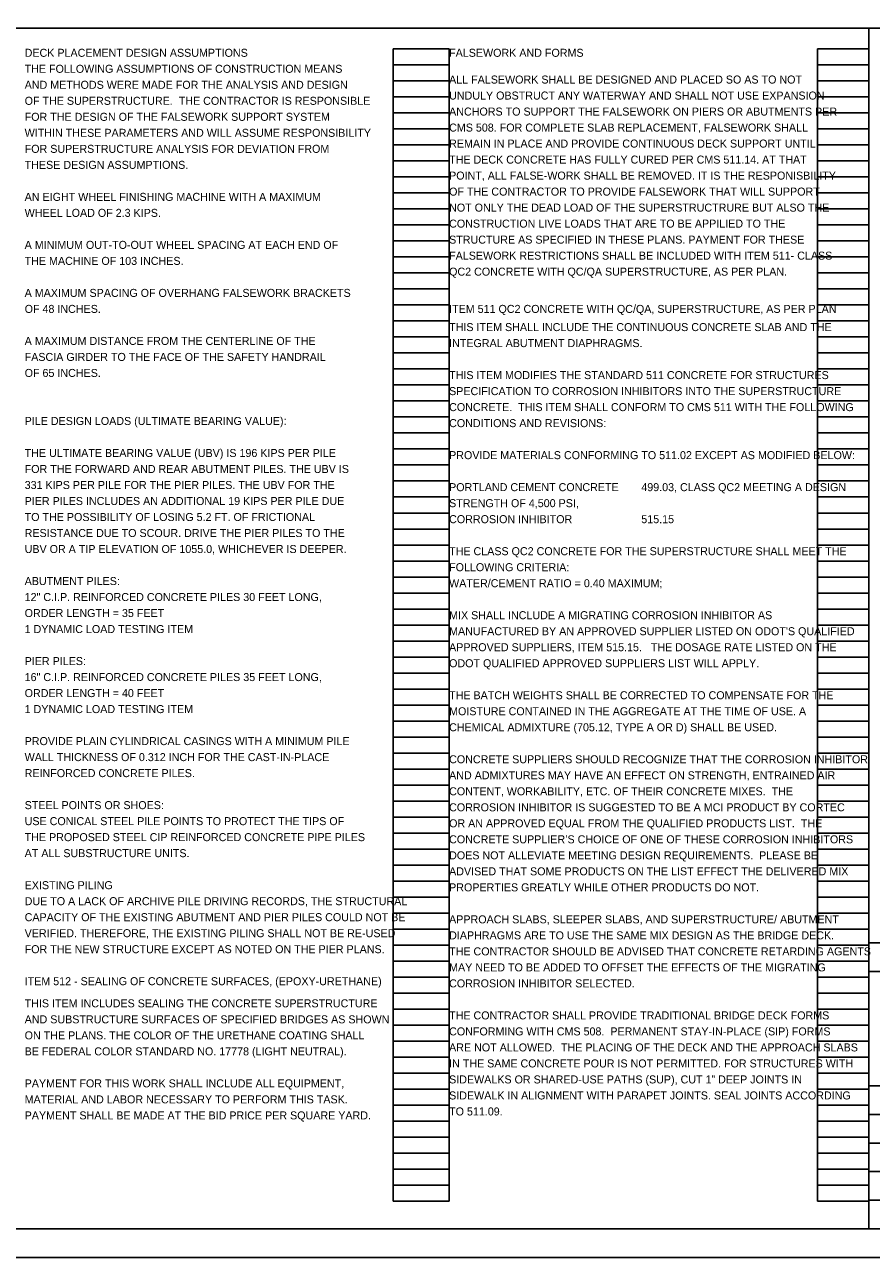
# Model space of a CAD drawing. Extents: x -15 to 144, y -80 to 40.
# Drawn here: x 17.24 to 32.04, y 0 to 21.56 of the extents above; entities that cross this region are included whole.
import ezdxf

# ---------------------------------------------------------------- set-up
doc = ezdxf.new("R2010")
doc.units = 0
for name, color, linetype in [('BR_P_Gen_Text', 7, 'Continuous'), ('Default', 7, 'Continuous'), ('SH_Cut_Line', 7, 'Continuous'), ('SH_Data', 7, 'Continuous'), ('SH_Text', 7, 'Continuous')]:
    doc.layers.add(name, color=color, linetype=linetype)

msp = doc.modelspace()

# ---------------------------------------------------------------- linework, layer by layer
at = {"layer": 'SH_Cut_Line'}
msp.add_lwpolyline([(0, 0), (34, 0), (34, 22), (0, 22)], close=True, dxfattribs=at)
at = {"layer": 'SH_Data'}
for p, q in [((32, 0.5), (32, 21.5)), ((32, 5.5), (33.5, 5.5)), ((32, 5), (33.5, 5)), ((32, 3), (33.5, 3)), ((32, 2.5), (33.5, 2.5)), ((32, 2), (33.5, 2)), ((32, 1.5), (33.5, 1.5)), ((32, 1), (33.5, 1))]:
    msp.add_line(p, q, dxfattribs=at)
msp.add_lwpolyline([(1.5, 21.5), (33.5, 21.5), (33.5, 0.5), (1.5, 0.5)], close=True, dxfattribs=at)
at = {"layer": 'SH_Text'}
for p, q in [((23.68, 0.98), (23.68, 21.14)), ((23.68, 21.14), (24.66, 21.14)), ((24.66, 0.98), (24.66, 21.14)), ((31.1, 0.98), (31.1, 21.14)), ((31.1, 21.14), (32, 21.14)), ((32, 0.98), (32, 21.14)), ((23.68, 20.86), (24.66, 20.86)), ((31.1, 20.86), (32, 20.86)), ((23.68, 20.58), (24.66, 20.58)), ((31.1, 20.58), (32, 20.58)), ((23.68, 20.3), (24.66, 20.3)), ((31.1, 20.3), (32, 20.3)), ((23.68, 20.02), (24.66, 20.02)), ((31.1, 20.02), (32, 20.02)), ((23.68, 19.74), (24.66, 19.74)), ((31.1, 19.74), (32, 19.74)), ((23.68, 19.46), (24.66, 19.46)), ((31.1, 19.46), (32, 19.46)), ((23.68, 19.18), (24.66, 19.18)), ((31.1, 19.18), (32, 19.18)), ((23.68, 18.9), (24.66, 18.9)), ((31.1, 18.9), (32, 18.9)), ((23.68, 18.62), (24.66, 18.62)), ((31.1, 18.62), (32, 18.62)), ((23.68, 18.34), (24.66, 18.34)), ((31.1, 18.34), (32, 18.34)), ((23.68, 18.06), (24.66, 18.06)), ((31.1, 18.06), (32, 18.06)), ((23.68, 17.78), (24.66, 17.78)), ((31.1, 17.78), (32, 17.78)), ((23.68, 17.5), (24.66, 17.5)), ((31.1, 17.5), (32, 17.5)), ((23.68, 17.22), (24.66, 17.22)), ((31.1, 17.22), (32, 17.22)), ((23.68, 16.94), (24.66, 16.94)), ((31.1, 16.94), (32, 16.94)), ((23.68, 16.66), (24.66, 16.66)), ((31.1, 16.66), (32, 16.66)), ((23.68, 16.38), (24.66, 16.38)), ((31.1, 16.38), (32, 16.38)), ((23.68, 16.1), (24.66, 16.1)), ((31.1, 16.1), (32, 16.1)), ((23.68, 15.82), (24.66, 15.82)), ((31.1, 15.82), (32, 15.82)), ((23.68, 15.54), (24.66, 15.54)), ((31.1, 15.54), (32, 15.54)), ((23.68, 15.26), (24.66, 15.26)), ((31.1, 15.26), (32, 15.26)), ((23.68, 14.98), (24.66, 14.98)), ((31.1, 14.98), (32, 14.98)), ((23.68, 14.7), (24.66, 14.7)), ((31.1, 14.7), (32, 14.7)), ((23.68, 14.42), (24.66, 14.42)), ((31.1, 14.42), (32, 14.42)), ((23.68, 14.14), (24.66, 14.14)), ((31.1, 14.14), (32, 14.14)), ((23.68, 13.86), (24.66, 13.86)), ((31.1, 13.86), (32, 13.86)), ((23.68, 13.58), (24.66, 13.58)), ((31.1, 13.58), (32, 13.58)), ((23.68, 13.3), (24.66, 13.3)), ((31.1, 13.3), (32, 13.3)), ((23.68, 13.02), (24.66, 13.02)), ((31.1, 13.02), (32, 13.02)), ((23.68, 12.74), (24.66, 12.74)), ((31.1, 12.74), (32, 12.74)), ((23.68, 12.46), (24.66, 12.46)), ((31.1, 12.46), (32, 12.46)), ((23.68, 12.18), (24.66, 12.18)), ((31.1, 12.18), (32, 12.18)), ((23.68, 11.9), (24.66, 11.9)), ((31.1, 11.9), (32, 11.9)), ((23.68, 11.62), (24.66, 11.62)), ((31.1, 11.62), (32, 11.62)), ((23.68, 11.34), (24.66, 11.34)), ((31.1, 11.34), (32, 11.34)), ((23.68, 11.06), (24.66, 11.06)), ((31.1, 11.06), (32, 11.06)), ((23.68, 10.78), (24.66, 10.78)), ((31.1, 10.78), (32, 10.78)), ((23.68, 10.5), (24.66, 10.5)), ((31.1, 10.5), (32, 10.5)), ((23.68, 10.22), (24.66, 10.22)), ((31.1, 10.22), (32, 10.22)), ((23.68, 9.94), (24.66, 9.94)), ((31.1, 9.94), (32, 9.94)), ((23.68, 9.66), (24.66, 9.66)), ((31.1, 9.66), (32, 9.66)), ((23.68, 9.38), (24.66, 9.38)), ((31.1, 9.38), (32, 9.38)), ((23.68, 9.1), (24.66, 9.1)), ((31.1, 9.1), (32, 9.1)), ((23.68, 8.82), (24.66, 8.82)), ((31.1, 8.82), (32, 8.82)), ((23.68, 8.54), (24.66, 8.54)), ((31.1, 8.54), (32, 8.54)), ((23.68, 8.26), (24.66, 8.26)), ((31.1, 8.26), (32, 8.26)), ((23.68, 7.98), (24.66, 7.98)), ((31.1, 7.98), (32, 7.98)), ((23.68, 7.7), (24.66, 7.7)), ((31.1, 7.7), (32, 7.7)), ((23.68, 7.42), (24.66, 7.42)), ((31.1, 7.42), (32, 7.42)), ((23.68, 7.14), (24.66, 7.14)), ((31.1, 7.14), (32, 7.14)), ((23.68, 6.86), (24.66, 6.86)), ((31.1, 6.86), (32, 6.86)), ((23.68, 6.58), (24.66, 6.58)), ((31.1, 6.58), (32, 6.58)), ((23.68, 6.3), (24.66, 6.3)), ((31.1, 6.3), (32, 6.3)), ((23.68, 6.02), (24.66, 6.02)), ((31.1, 6.02), (32, 6.02)), ((23.68, 5.74), (24.66, 5.74)), ((31.1, 5.74), (32, 5.74)), ((23.68, 5.46), (24.66, 5.46)), ((31.1, 5.46), (32, 5.46)), ((23.68, 5.18), (24.66, 5.18)), ((31.1, 5.18), (32, 5.18)), ((23.68, 4.9), (24.66, 4.9)), ((31.1, 4.9), (32, 4.9)), ((23.68, 4.62), (24.66, 4.62)), ((31.1, 4.62), (32, 4.62)), ((23.68, 4.34), (24.66, 4.34)), ((31.1, 4.34), (32, 4.34)), ((23.68, 4.06), (24.66, 4.06)), ((31.1, 4.06), (32, 4.06)), ((23.68, 3.78), (24.66, 3.78)), ((31.1, 3.78), (32, 3.78)), ((23.68, 3.5), (24.66, 3.5)), ((31.1, 3.5), (32, 3.5)), ((23.68, 3.22), (24.66, 3.22)), ((31.1, 3.22), (32, 3.22)), ((23.68, 2.94), (24.66, 2.94)), ((31.1, 2.94), (32, 2.94)), ((23.68, 2.66), (24.66, 2.66)), ((31.1, 2.66), (32, 2.66)), ((23.68, 2.38), (24.66, 2.38)), ((31.1, 2.38), (32, 2.38)), ((23.68, 2.1), (24.66, 2.1)), ((31.1, 2.1), (32, 2.1)), ((23.68, 1.82), (24.66, 1.82)), ((31.1, 1.82), (32, 1.82)), ((23.68, 1.54), (24.66, 1.54)), ((31.1, 1.54), (32, 1.54)), ((23.68, 1.26), (24.66, 1.26)), ((31.1, 1.26), (32, 1.26)), ((23.68, 0.98), (24.66, 0.98)), ((31.1, 0.98), (32, 0.98))]:
    msp.add_line(p, q, dxfattribs=at)

# ---------------------------------------------------------------- texts
at = {"layer": 'BR_P_Gen_Text'}
for s, p in [('DECK PLACEMENT DESIGN ASSUMPTIONS', (17.24, 21)), ('FALSEWORK AND FORMS', (24.66, 21)), ('THE FOLLOWING ASSUMPTIONS OF CONSTRUCTION MEANS', (17.24, 20.72)), ('AND METHODS WERE MADE FOR THE ANALYSIS AND DESIGN', (17.24, 20.44)), ('ALL FALSEWORK SHALL BE DESIGNED AND PLACED SO AS TO NOT ', (24.66, 20.532)), ('OF THE SUPERSTRUCTURE.  THE CONTRACTOR IS RESPONSIBLE', (17.24, 20.16)), ('UNDULY OBSTRUCT ANY WATERWAY AND SHALL NOT USE EXPANSION ', (24.66, 20.252)), ('ANCHORS TO SUPPORT THE FALSEWORK ON PIERS OR ABUTMENTS PER ', (24.66, 19.972)), ('FOR THE DESIGN OF THE FALSEWORK SUPPORT SYSTEM', (17.24, 19.88)), ('WITHIN THESE PARAMETERS AND WILL ASSUME RESPONSIBILITY', (17.24, 19.6)), ('CMS 508. FOR COMPLETE SLAB REPLACEMENT, FALSEWORK SHALL ', (24.66, 19.692)), ('FOR SUPERSTRUCTURE ANALYSIS FOR DEVIATION FROM ', (17.24, 19.32)), ('REMAIN IN PLACE AND PROVIDE CONTINUOUS DECK SUPPORT UNTIL ', (24.66, 19.412)), ('THE DECK CONCRETE HAS FULLY CURED PER CMS 511.14. AT THAT ', (24.66, 19.132)), ('THESE DESIGN ASSUMPTIONS.', (17.24, 19.04)), ('POINT, ALL FALSE-WORK SHALL BE REMOVED. IT IS THE RESPONISBILITY ', (24.66, 18.852)), ('AN EIGHT WHEEL FINISHING MACHINE WITH A MAXIMUM', (17.24, 18.48)), ('OF THE CONTRACTOR TO PROVIDE FALSEWORK THAT WILL SUPPORT ', (24.66, 18.572)), ('WHEEL LOAD OF 2.3 KIPS.', (17.24, 18.2)), ('NOT ONLY THE DEAD LOAD OF THE SUPERSTRUCTRURE BUT ALSO THE ', (24.66, 18.292)), ('CONSTRUCTION LIVE LOADS THAT ARE TO BE APPILIED TO THE ', (24.66, 18.012)), ('A MINIMUM OUT-TO-OUT WHEEL SPACING AT EACH END OF', (17.24, 17.64)), ('STRUCTURE AS SPECIFIED IN THESE PLANS. PAYMENT FOR THESE ', (24.66, 17.732)), ('THE MACHINE OF 103 INCHES.', (17.24, 17.36)), ('FALSEWORK RESTRICTIONS SHALL BE INCLUDED WITH ITEM 511- CLASS ', (24.66, 17.452)), ('QC2 CONCRETE WITH QC/QA SUPERSTRUCTURE, AS PER PLAN. ', (24.66, 17.172)), ('A MAXIMUM SPACING OF OVERHANG FALSEWORK BRACKETS', (17.24, 16.8)), ('OF 48 INCHES.', (17.24, 16.52)), ('ITEM 511 QC2 CONCRETE WITH QC/QA, SUPERSTRUCTURE, AS PER PLAN', (24.66, 16.52)), ('THIS ITEM SHALL INCLUDE THE CONTINUOUS CONCRETE SLAB AND THE', (24.66, 16.202)), ('A MAXIMUM DISTANCE FROM THE CENTERLINE OF THE', (17.24, 15.96)), ('INTEGRAL ABUTMENT DIAPHRAGMS. ', (24.66, 15.922)), ('FASCIA GIRDER TO THE FACE OF THE SAFETY HANDRAIL', (17.24, 15.68)), ('OF 65 INCHES.', (17.24, 15.4)), ('THIS ITEM MODIFIES THE STANDARD 511 CONCRETE FOR STRUCTURES ', (24.66, 15.362)), ('SPECIFICATION TO CORROSION INHIBITORS INTO THE SUPERSTRUCTURE ', (24.66, 15.082)), ('CONCRETE.  THIS ITEM SHALL CONFORM TO CMS 511 WITH THE FOLLOWING ', (24.66, 14.802)), ('CONDITIONS AND REVISIONS:', (24.66, 14.522)), ('PROVIDE MATERIALS CONFORMING TO 511.02 EXCEPT AS MODIFIED BELOW:', (24.66, 13.962)), ('PORTLAND CEMENT CONCRETE', (24.66, 13.402)), ('499.03, CLASS QC2 MEETING A DESIGN ', (28.02, 13.402)), ('STRENGTH OF 4,500 PSI, ', (24.66, 13.122)), ('CORROSION INHIBITOR', (24.66, 12.842)), ('515.15', (28.02, 12.842)), ('THE CLASS QC2 CONCRETE FOR THE SUPERSTRUCTURE SHALL MEET THE ', (24.66, 12.282)), ('FOLLOWING CRITERIA:', (24.66, 12.002)), ('WATER/CEMENT RATIO = 0.40 MAXIMUM;  ', (24.66, 11.722)), ('MIX SHALL INCLUDE A MIGRATING CORROSION INHIBITOR AS ', (24.66, 11.162)), ("MANUFACTURED BY AN APPROVED SUPPLIER LISTED ON ODOT'S QUALIFIED ", (24.66, 10.882)), ('APPROVED SUPPLIERS, ITEM 515.15.   THE DOSAGE RATE LISTED ON THE ', (24.66, 10.602)), ('ODOT QUALIFIED APPROVED SUPPLIERS LIST WILL APPLY.  ', (24.66, 10.322)), ('THE BATCH WEIGHTS SHALL BE CORRECTED TO COMPENSATE FOR THE ', (24.66, 9.762)), ('MOISTURE CONTAINED IN THE AGGREGATE AT THE TIME OF USE. A ', (24.66, 9.482)), ('CHEMICAL ADMIXTURE (705.12, TYPE A OR D) SHALL BE USED. ', (24.66, 9.202)), ('CONCRETE SUPPLIERS SHOULD RECOGNIZE THAT THE CORROSION INHIBITOR ', (24.66, 8.642)), ('AND ADMIXTURES MAY HAVE AN EFFECT ON STRENGTH, ENTRAINED AIR ', (24.66, 8.362)), ('CONTENT, WORKABILITY, ETC. OF THEIR CONCRETE MIXES.  THE ', (24.66, 8.082)), ('CORROSION INHIBITOR IS SUGGESTED TO BE A MCI PRODUCT BY CORTEC ', (24.66, 7.802)), ('OR AN APPROVED EQUAL FROM THE QUALIFIED PRODUCTS LIST.  THE ', (24.66, 7.522)), ('CONCRETE SUPPLIER’S CHOICE OF ONE OF THESE CORROSION INHIBITORS ', (24.66, 7.242)), ('DOES NOT ALLEVIATE MEETING DESIGN REQUIREMENTS.  PLEASE BE ', (24.66, 6.962)), ('ADVISED THAT SOME PRODUCTS ON THE LIST EFFECT THE DELIVERED MIX ', (24.66, 6.682)), ('EXISTING PILING', (17.24, 6.44)), ('PROPERTIES GREATLY WHILE OTHER PRODUCTS DO NOT.', (24.66, 6.402)), ('DUE TO A LACK OF ARCHIVE PILE DRIVING RECORDS, THE STRUCTURAL', (17.24, 6.16)), ('CAPACITY OF THE EXISTING ABUTMENT AND PIER PILES COULD NOT BE', (17.24, 5.88)), ('APPROACH SLABS, SLEEPER SLABS, AND SUPERSTRUCTURE/ ABUTMENT ', (24.66, 5.842)), ('VERIFIED. THEREFORE, THE EXISTING PILING SHALL NOT BE RE-USED', (17.24, 5.6)), ('DIAPHRAGMS ARE TO USE THE SAME MIX DESIGN AS THE BRIDGE DECK.  ', (24.66, 5.562)), ('FOR THE NEW STRUCTURE EXCEPT AS NOTED ON THE PIER PLANS.', (17.24, 5.32)), ('THE CONTRACTOR SHOULD BE ADVISED THAT CONCRETE RETARDING AGENTS ', (24.66, 5.282)), ('MAY NEED TO BE ADDED TO OFFSET THE EFFECTS OF THE MIGRATING ', (24.66, 5.002)), ('ITEM 512 - SEALING OF CONCRETE SURFACES, (EPOXY-URETHANE)', (17.24, 4.76)), ('CORROSION INHIBITOR SELECTED.  ', (24.66, 4.722)), ('THIS ITEM INCLUDES SEALING THE CONCRETE SUPERSTRUCTURE', (17.24, 4.373)), ('AND SUBSTRUCTURE SURFACES OF SPECIFIED BRIDGES AS SHOWN', (17.24, 4.093)), ('THE CONTRACTOR SHALL PROVIDE TRADITIONAL BRIDGE DECK FORMS ', (24.66, 4.162)), ('ON THE PLANS. THE COLOR OF THE URETHANE COATING SHALL', (17.24, 3.813)), ('CONFORMING WITH CMS 508.  PERMANENT STAY-IN-PLACE (SIP) FORMS ', (24.66, 3.882)), ('BE FEDERAL COLOR STANDARD NO. 17778 (LIGHT NEUTRAL).', (17.24, 3.533)), ('ARE NOT ALLOWED.  THE PLACING OF THE DECK AND THE APPROACH SLABS ', (24.66, 3.602)), ('IN THE SAME CONCRETE POUR IS NOT PERMITTED. FOR STRUCTURES WITH ', (24.66, 3.322)), ('PAYMENT FOR THIS WORK SHALL INCLUDE ALL EQUIPMENT,', (17.24, 2.973)), ('SIDEWALKS OR SHARED-USE PATHS (SUP), CUT 1” DEEP JOINTS IN ', (24.66, 3.042)), ('MATERIAL AND LABOR NECESSARY TO PERFORM THIS TASK.', (17.24, 2.693)), ('SIDEWALK IN ALIGNMENT WITH PARAPET JOINTS. SEAL JOINTS ACCORDING ', (24.66, 2.762)), ('TO 511.09.', (24.66, 2.482)), ('PAYMENT SHALL BE MADE AT THE BID PRICE PER SQUARE YARD.', (17.24, 2.413))]:
    msp.add_text(s, height=0.14, dxfattribs=at).set_placement(p)
at = {"layer": 'Default'}
for s, p in [('PILE DESIGN LOADS (ULTIMATE BEARING VALUE): ', (17.24, 14.56)), ('THE ULTIMATE BEARING VALUE (UBV) IS 196 KIPS PER PILE ', (17.24, 14)), ('FOR THE FORWARD AND REAR ABUTMENT PILES. THE UBV IS ', (17.24, 13.72)), ('331 KIPS PER PILE FOR THE PIER PILES. THE UBV FOR THE ', (17.24, 13.44)), ('PIER PILES INCLUDES AN ADDITIONAL 19 KIPS PER PILE DUE ', (17.24, 13.16)), ('TO THE POSSIBILITY OF LOSING 5.2 FT. OF FRICTIONAL ', (17.24, 12.88)), ('RESISTANCE DUE TO SCOUR. DRIVE THE PIER PILES TO THE ', (17.24, 12.6)), ('UBV OR A TIP ELEVATION OF 1055.0, WHICHEVER IS DEEPER.', (17.24, 12.32)), ('ABUTMENT PILES:', (17.24, 11.76)), ('12" C.I.P. REINFORCED CONCRETE PILES 30 FEET LONG, ', (17.24, 11.48)), ('ORDER LENGTH = 35 FEET', (17.24, 11.2)), ('1 DYNAMIC LOAD TESTING ITEM', (17.24, 10.92)), ('PIER PILES:', (17.24, 10.36)), ('16" C.I.P. REINFORCED CONCRETE PILES 35 FEET LONG, ', (17.24, 10.08)), ('ORDER LENGTH = 40 FEET', (17.24, 9.8)), ('1 DYNAMIC LOAD TESTING ITEM', (17.24, 9.52)), ('PROVIDE PLAIN CYLINDRICAL CASINGS WITH A MINIMUM PILE ', (17.24, 8.96)), ('WALL THICKNESS OF 0.312 INCH FOR THE CAST-IN-PLACE ', (17.24, 8.68)), ('REINFORCED CONCRETE PILES.', (17.24, 8.4)), ('STEEL POINTS OR SHOES:', (17.24, 7.84)), ('USE CONICAL STEEL PILE POINTS TO PROTECT THE TIPS OF ', (17.24, 7.56)), ('THE PROPOSED STEEL CIP REINFORCED CONCRETE PIPE PILES ', (17.24, 7.28)), ('AT ALL SUBSTRUCTURE UNITS.', (17.24, 7))]:
    msp.add_text(s, height=0.14, dxfattribs=at).set_placement(p)

doc.saveas('drawing.dxf')
